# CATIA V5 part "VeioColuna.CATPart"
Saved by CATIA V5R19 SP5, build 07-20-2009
Part number: VeioColuna
Bounding box of the stored display mesh (mm): x -17.954 to 17.954, y -55 to 35, z -17.954 to 17.954
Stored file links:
  Z:\UA\ATLAS\atlascar\ServoPiloto\dir\suportePotenciometro\V2\VeioColuna.CATPart
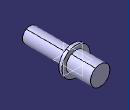
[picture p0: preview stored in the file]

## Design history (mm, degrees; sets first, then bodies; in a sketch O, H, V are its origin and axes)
Body1 (main body)
  Sketch1 on yz-plane, origin (0, 0, 0), H (0, 1, 0), V (0, 0, 1)
    line L1 (-55, 9.5) -> (0, 9.5)
    point P2 (0, 9.5)
    line L2 (0, 9.5) -> (0, 18)
    line L3 (0, 18) -> (4, 18)
    line L4 (4, 18) -> (4, 12.5)
    line L5 (4, 12.5) -> (35, 12.5)
    line L6 (35, 12.5) -> (35, 0)
    point P7 (35, 0)
    line L7 (35, 0) -> (-55, 0)
    line L8 (-55, 0) -> (-55, 9.5)
    distance L2 L4 = 4
    distance L3 L7 = 18
    distance L1 L7 = 9.5
    distance L5 L7 = 12.5
    distance L6 V = 35
    distance L2 L8 = 55
    coincidence: P2 V, P7 H
    horizontal: L1 H, L3 H, L5 H, L7 H
    vertical: L2 V, L4 V, L6 V, L8 V
  Shaft1: profile Sketch1, axis Sketch1.H, angle 360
